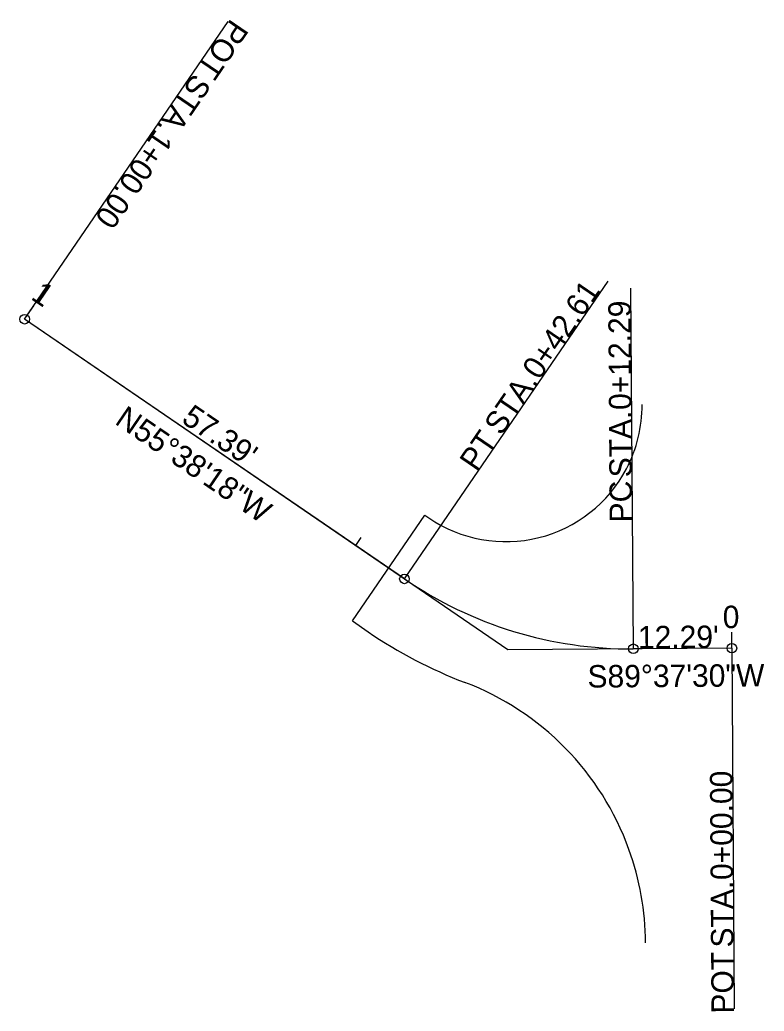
# Model space of a CAD drawing. Extents: x 2284130 to 2285210, y 587171 to 587339.
# Drawn here: x 2284344.6 to 2284437.4, y 587186.3 to 587310 of the extents above; entities that cross this region are included whole.
import ezdxf

# ---------------------------------------------------------------- set-up
doc = ezdxf.new("R2010")
doc.units = 0
for name, color, linetype in [('DT_X_Triangles', 7, 'Continuous'), ('GE_P_Alignment', 7, 'Continuous'), ('GE_P_Alignment_100_Bearings', 7, 'Continuous'), ('GE_P_Alignment_100_Cardinal_Points', 7, 'Continuous'), ('GE_P_Alignment_100_Distances', 7, 'Continuous'), ('GE_P_Alignment_100_Stations', 7, 'Continuous')]:
    doc.layers.add(name, color=color, linetype=linetype)

msp = doc.modelspace()

# ---------------------------------------------------------------- linework, layer by layer
at = {"layer": 'DT_X_Triangles'}
for p, q in [((2284386.07, 587234.99), (2284395.1, 587248.19)), ((2284395.1, 587248.19), (2284395.61, 587247.85)), ((2284386.07, 587234.99), (2284388.04, 587233.64))]:
    msp.add_line(p, q, dxfattribs=at)
for centre, radius, start, end in [((2284405.2, 587261.88), 17, 332.3026, 0.3751), ((2284405.2, 587261.88), 17, 235.6382, 332.3026), ((2284420.78, 587281.51), 58, 235.6382, 249.1262), ((2284387.64, 587194.62), 35, 19.838, 69.1262), ((2284387.64, 587194.62), 35, 0.3751, 19.838)]:
    msp.add_arc(centre, radius, start, end, dxfattribs=at)
at = {"layer": 'GE_P_Alignment'}
for p, q in [((2284405.47, 587231.41), (2284345.18, 587272.63)), ((2284392.56, 587240.24), (2284345.18, 587272.63)), ((2284433.4, 587231.6), (2284405.47, 587231.41)), ((2284433.4, 587231.6), (2284421.11, 587231.52))]:
    msp.add_line(p, q, dxfattribs=at)
msp.add_arc((2284420.78, 587281.51), 50, 235.6382, 270.3751, dxfattribs=at)
msp.add_arc((2284420.78, 587281.51), 50, 235.6382, 270.3751, dxfattribs=at)
at = {"layer": 'GE_P_Alignment_100_Cardinal_Points'}
for p, q in [((2284345.18, 587272.63), (2284370.58, 587309.78)), ((2284392.56, 587240.24), (2284417.96, 587277.39)), ((2284421.11, 587231.52), (2284420.81, 587276.51)), ((2284433.4, 587231.6), (2284433.7, 587186.6))]:
    msp.add_line(p, q, dxfattribs=at)
for centre in [(2284345.18, 587272.63), (2284392.56, 587240.24), (2284421.11, 587231.52), (2284433.4, 587231.6)]:
    msp.add_circle(centre, 0.6, dxfattribs=at)
at = {"layer": 'GE_P_Alignment_100_Stations'}
for p, q in [((2284345.18, 587272.63), (2284346.31, 587274.28)), ((2284387.13, 587245.4), (2284386.46, 587244.41)), ((2284433.4, 587231.6), (2284433.39, 587233.6))]:
    msp.add_line(p, q, dxfattribs=at)

# ---------------------------------------------------------------- texts
at = {"layer": 'GE_P_Alignment_100_Bearings'}
for s, rotation, p in [('N55°38\'18"W', 325.6382, (2284356.3, 587259.66)), ('S89°37\'30"W', 0.3751, (2284415.4, 587226.68))]:
    msp.add_text(s, height=2.8, rotation=rotation, dxfattribs=at).set_placement(p)
at = {"layer": 'GE_P_Alignment_100_Cardinal_Points'}
for s, rotation, p in [('POT', 235.6382, (2284370.93, 587310.22)), (' STA. ', 235.6382, (2284366.87, 587304.28)), ('1+00.00', 235.6382, (2284361.53, 587296.48)), ('0+42.61', 55.6382, (2284409.39, 587264.94)), ('0+12.29', 90.3751, (2284420.87, 587261.32)), (' STA. ', 55.6382, (2284404.06, 587257.14)), (' STA. ', 90.3751, (2284420.93, 587251.87)), ('PT', 55.6382, (2284401.57, 587253.49)), ('PC', 90.3751, (2284420.96, 587247.29)), ('0+00.00', 90.3751, (2284433.55, 587202.69)), (' STA. ', 90.3751, (2284433.61, 587193.23)), ('POT', 90.3751, (2284433.66, 587186.03))]:
    msp.add_text(s, height=2.8, rotation=rotation, dxfattribs=at).set_placement(p)
at = {"layer": 'GE_P_Alignment_100_Distances'}
for s, rotation, p in [("57.39'", 325.6382, (2284364.61, 587259.84)), ("12.29'", 0.3751, (2284421.69, 587231.56))]:
    msp.add_text(s, height=2.8, rotation=rotation, dxfattribs=at).set_placement(p)
at = {"layer": 'GE_P_Alignment_100_Stations'}
for s, rotation, p in [('1', 325.6382, (2284345.84, 587275.21)), ('0', 0.3751, (2284432.27, 587234.09))]:
    msp.add_text(s, height=2.8, rotation=rotation, dxfattribs=at).set_placement(p)

doc.saveas('drawing.dxf')
